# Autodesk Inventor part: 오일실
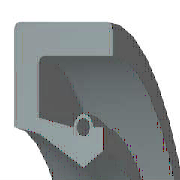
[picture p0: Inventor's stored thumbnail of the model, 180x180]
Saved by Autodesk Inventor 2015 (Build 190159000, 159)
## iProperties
IsCustomPart: 1
Created: 2015-10
Part Number: 오일실
Material: 고무
Description: 오일-실
Document SubType Name: Modeling
Standard: KS B 2804
Designer: mdu
Standards Organization: KS
Language: ko-KR
Size Designation: S - 25 38 8
Categories: <MemberInstance><Categories><Category DisplayName="샤프트 부품" InternalName="7f7aeb1f-a693-4053-b835-cee3144e0d98" Mnemonic="SHFT"><Category DisplayName="실링" Intern
Density: 0.93 g/cm^3
Appearance: 고무 - 검은색 - 버전 1.1
Mass: 2.23721 g
Surface Area: 37.0166 cm^2
Volume: 2.4056 cm^3
Author: mdu
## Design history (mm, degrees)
revolve "본체" stored, may be unused: angle "d17" = 90 deg
revolve "스프링1" stored, may be unused: angle "d18" = 90 deg
body "Solid1"
sketch "스케치1"
  geometry: L1 (0, 19)-(8, 19); L2 (8, 19)-(8, 17.75); L3 (8, 17.75)-(1.75, 17.75); L4 (0, 19)-(0, 14.6); L5 (0, 14.6)-(1.75, 14.25); L6 (1.75, 14.25)-(4.9, 12.5); L7 (4.9, 12.5)-(0, 12.5); L8 (6.3, 13.375)-(6.3, 14.6); L9 (0, 0)-(9.586, 0) reference; L10 (4.9, 12.5)-(6.3, 13.375); L11 (0, 18)-(0, -3) reference; L12 (-1.917, 0)-(11.503, 0) reference; L13 (4.2, 14.6)-(1.75, 15.09); L14 (1.75, 15.09)-(1.75, 17.75); L15 (6.3, 14.6)-(5.6, 14.6); C1 r 0.455 at (4.9, 14.6); A1 r 0.7 centre (4.9, 14.6) between (5.6, 14.6) and (4.2, 14.6)
  constraints: 26 end point, 5 horizontal alignment, 4 perpendicular, 2 centre point, 2 collinear, 2 horizontal, 2 parallel, 2 point on circle, 2 point on line, 2 vertical alignment, 1 coincident
  dimensions: "d0" = 38 diameter of L1 L9 (= SD2); "d1" = 26.75 diameter of L8.start L9 (= ABDM); "d2" = 1.25 distance of L1.end L2.end (computed from SD); "d3" = 0.91 diameter of C1 (= SPDI); "d4" = 1.4 diameter of A1 (= SPDA); "d5" = 25 diameter of L6.end L9 (= NND); "d6" = 28.5 diameter of L5.end L9 (= TKDM); "d7" = 29.2 diameter of L4.end L9 (= HLDM); "d8" = 4.9 distance from line of C1.centre L4 (= SPDST); "d9" = 6.3 distance between parallel lines of L8 L4 (= SDI); "d10" = 8 distance between parallel lines of L2 L4 (= SWDT); "d12" = 1.75 distance between parallel lines of L14 L4 (= SD)
fillet "모깎기1" dims "d11" = 0.3 (= RR)
other parameters: "SD2" = 38 [user parameter; used in 1 equation term], "SWDT" = 8 [user parameter; used in 1 equation term], "RR" = 0.3 [user parameter; used in 1 equation term], "SD" = 1.75 [user parameter; used in 2 equation terms], "NND" = 25 [user parameter; used in 1 equation term], "SPDA" = 1.4 [user parameter; used in 1 equation term], "SPDI" = 0.91 [user parameter; used in 1 equation term], "TKDM" = 28.5 [user parameter; used in 1 equation term], "HLDM" = 29.2 [user parameter; used in 1 equation term], "ABDM" = 26.75 [user parameter; used in 1 equation term], "SDI" = 6.3 [user parameter; used in 1 equation term], "SPDST" = 4.9 [user parameter; used in 1 equation term], "d13" = 0, "d14" = 0, "d15" = 0, "LAB" = 0.35 [user parameter]
